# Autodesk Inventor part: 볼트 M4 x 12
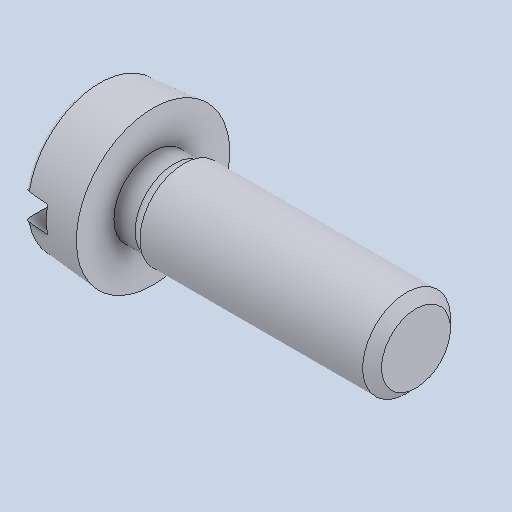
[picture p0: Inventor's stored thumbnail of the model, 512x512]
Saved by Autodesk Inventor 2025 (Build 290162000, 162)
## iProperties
Created: 2024-07
Part Number: 볼트 M4 x 12
Material: 강철, 연강
Description: 6각머리 태핑 나사
Document SubType Name: Modeling
Designer: samsung
Density: 7.85 g/cm^3
Appearance: 기본값
Author: jhkim
Sending System: Autodesk Inventor 2025
Preprocessor: ST-DEVELOPER v20
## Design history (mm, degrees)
feature "Solid1"
node "솔리드1"
